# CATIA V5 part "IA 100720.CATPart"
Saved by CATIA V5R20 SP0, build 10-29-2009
Part number: IA 100720
Revision: ANY
Definition: UNKNOWN
Nomenclature: IA 100720
Source: Unknown
Bounding box of the stored display mesh (mm): x -5.35 to 5.35, y -17 to 0, z -5.35 to 5.35
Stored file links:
  C:\Users\Utente\Desktop\IO LAVORO\3D X SITO CF\CUMSA\3D files FA\FA 200712-20\IA 100720.CATPart
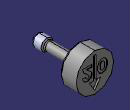
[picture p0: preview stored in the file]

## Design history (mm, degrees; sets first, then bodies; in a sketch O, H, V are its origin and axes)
Body1 "Cortar-Extruir3" (main body)
  Solid1: solid without history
